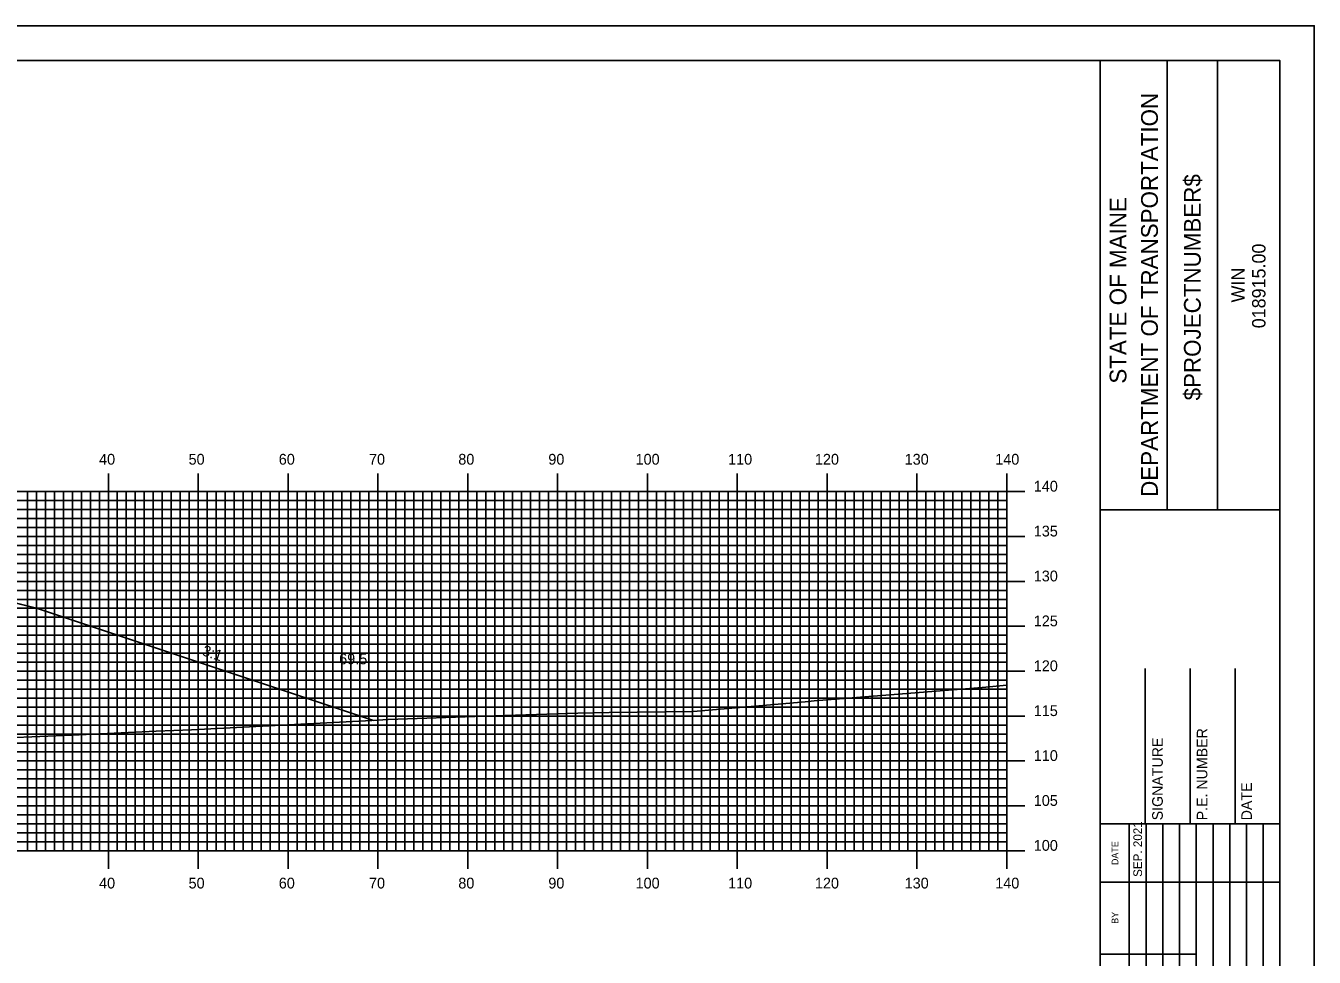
# Model space of a CAD drawing. Extents: x 1781860 to 1782203, y 442591 to 442811.
# Drawn here: x 1782056.7 to 1782200.1, y 442706.8 to 442810.5 of the extents above; entities that cross this region are included whole.
import ezdxf

# ---------------------------------------------------------------- set-up
doc = ezdxf.new("R2010")
doc.units = 0
for name, color, linetype in [('ANNOTATION', 7, 'Continuous'), ('BORDER', 7, 'Continuous'), ('D_Roadway_Centerline', 7, 'Continuous'), ('D_Roadway_SlopeLines', 7, 'Continuous'), ('D_Text_Standard', 7, 'Continuous'), ('H_V ANNOTATION', 7, 'Continuous'), ('MAJOR', 7, 'Continuous'), ('MINOR', 7, 'Continuous'), ('PLOT BOUNDARY', 7, 'Continuous'), ('S_Roadway_Centerline', 7, 'Continuous')]:
    doc.layers.add(name, color=color, linetype=linetype)

msp = doc.modelspace()

# ---------------------------------------------------------------- linework, layer by layer
at = {"layer": 'BORDER'}
for p, q in [((1782176.32, 442596.67), (1782176.32, 442806.67)), ((1782183.78, 442756.66), (1782183.78, 442806.66)), ((1782189.37, 442756.66), (1782189.37, 442806.66)), ((1782176.32, 442756.65), (1782196.32, 442756.65)), ((1782181.32, 442721.67), (1782181.32, 442738.97)), ((1782186.32, 442721.67), (1782186.32, 442738.97)), ((1782191.32, 442721.67), (1782191.32, 442738.97)), ((1782176.32, 442721.67), (1782196.32, 442721.67))]:
    msp.add_line(p, q, dxfattribs=at)
msp.add_lwpolyline([(1781876.32, 442596.67), (1782196.32, 442596.67), (1782196.32, 442806.67), (1781876.32, 442806.67)], close=True, dxfattribs=at)
for points in [[(1782179.55, 442715.17), (1782179.55, 442721.67)], [(1782181.42, 442686.68), (1782181.42, 442721.67)], [(1782183.28, 442721.67), (1782183.28, 442686.68)], [(1782185.14, 442686.68), (1782185.14, 442721.67)], [(1782187.01, 442686.68), (1782187.01, 442721.67)], [(1782188.87, 442686.68), (1782188.87, 442721.67)], [(1782190.73, 442686.68), (1782190.73, 442721.67)], [(1782192.6, 442686.68), (1782192.6, 442721.67)], [(1782194.46, 442686.68), (1782194.46, 442721.67)], [(1782179.55, 442686.68), (1782179.55, 442720.26)], [(1782176.32, 442715.17), (1782196.32, 442715.17)], [(1782176.32, 442707.17), (1782179.55, 442707.17)], [(1782179.55, 442707.17), (1782187, 442707.17)]]:
    msp.add_lwpolyline(points, dxfattribs=at)
at = {"layer": 'D_Roadway_Centerline'}
msp.add_lwpolyline([(1781943.4, 442728.84), (1781993.92, 442745.68), (1781995.75, 442746.13), (1782005.92, 442748.68), (1782013.92, 442749), (1782025.92, 442749.24), (1782037.92, 442749), (1782045.92, 442748.68), (1782056.09, 442746.13), (1782057.92, 442745.68), (1782095.42, 442733.18)], dxfattribs=at)
at = {"layer": 'D_Roadway_SlopeLines'}
msp.add_lwpolyline([(1782045.92, 442748.68), (1782057.92, 442745.68), (1782095.42, 442733.18)], dxfattribs=at)
at = {"layer": 'MAJOR'}
for p, q in [((1782065.92, 442760.67), (1782065.92, 442758.67)), ((1782075.92, 442760.67), (1782075.92, 442758.67)), ((1782085.92, 442760.67), (1782085.92, 442758.67)), ((1782095.92, 442760.67), (1782095.92, 442758.67)), ((1782105.92, 442760.67), (1782105.92, 442758.67)), ((1782115.92, 442760.67), (1782115.92, 442758.67)), ((1782125.92, 442760.67), (1782125.92, 442758.67)), ((1782135.92, 442760.67), (1782135.92, 442758.67)), ((1782145.92, 442760.67), (1782145.92, 442758.67)), ((1782155.92, 442760.67), (1782155.92, 442758.67)), ((1782165.92, 442760.67), (1782165.92, 442758.67)), ((1781885.92, 442758.67), (1782165.92, 442758.67)), ((1781885.92, 442758.67), (1782165.92, 442758.67)), ((1782065.92, 442718.67), (1782065.92, 442758.67)), ((1782075.92, 442718.67), (1782075.92, 442758.67)), ((1782085.92, 442718.67), (1782085.92, 442758.67)), ((1782095.92, 442718.67), (1782095.92, 442758.67)), ((1782105.92, 442718.67), (1782105.92, 442758.67)), ((1782115.92, 442718.67), (1782115.92, 442758.67)), ((1782125.92, 442718.67), (1782125.92, 442758.67)), ((1782135.92, 442718.67), (1782135.92, 442758.67)), ((1782145.92, 442718.67), (1782145.92, 442758.67)), ((1782155.92, 442718.67), (1782155.92, 442758.67)), ((1782167.92, 442758.67), (1782163.92, 442758.67)), ((1782165.92, 442718.67), (1782165.92, 442758.67)), ((1782165.92, 442718.67), (1782165.92, 442758.67)), ((1781885.92, 442753.67), (1782165.92, 442753.67)), ((1782167.92, 442753.67), (1782163.92, 442753.67)), ((1781885.92, 442748.67), (1782165.92, 442748.67)), ((1782167.92, 442748.67), (1782163.92, 442748.67)), ((1781885.92, 442743.67), (1782165.92, 442743.67)), ((1782167.92, 442743.67), (1782163.92, 442743.67)), ((1781885.92, 442738.67), (1782165.92, 442738.67)), ((1782167.92, 442738.67), (1782163.92, 442738.67)), ((1781885.92, 442733.67), (1782165.92, 442733.67)), ((1782167.92, 442733.67), (1782163.92, 442733.67)), ((1781885.92, 442728.67), (1782165.92, 442728.67)), ((1782167.92, 442728.67), (1782163.92, 442728.67)), ((1781885.92, 442723.67), (1782165.92, 442723.67)), ((1782167.92, 442723.67), (1782163.92, 442723.67)), ((1781885.92, 442718.67), (1782165.92, 442718.67)), ((1781885.92, 442718.67), (1782165.92, 442718.67)), ((1782065.92, 442716.66), (1782065.92, 442718.67)), ((1782075.92, 442716.66), (1782075.92, 442718.67)), ((1782085.92, 442716.66), (1782085.92, 442718.67)), ((1782095.92, 442716.66), (1782095.92, 442718.67)), ((1782105.92, 442716.66), (1782105.92, 442718.67)), ((1782115.92, 442716.66), (1782115.92, 442718.67)), ((1782125.92, 442716.66), (1782125.92, 442718.67)), ((1782135.92, 442716.66), (1782135.92, 442718.67)), ((1782145.92, 442716.66), (1782145.92, 442718.67)), ((1782155.92, 442716.66), (1782155.92, 442718.67)), ((1782167.92, 442718.67), (1782163.92, 442718.67)), ((1782165.92, 442716.66), (1782165.92, 442718.67))]:
    msp.add_line(p, q, dxfattribs=at)
at = {"layer": 'MINOR'}
for p, q in [((1782056.92, 442718.67), (1782056.92, 442758.67)), ((1782057.92, 442718.67), (1782057.92, 442758.67)), ((1782058.92, 442718.67), (1782058.92, 442758.67)), ((1782059.92, 442718.67), (1782059.92, 442758.67)), ((1782060.92, 442718.67), (1782060.92, 442758.67)), ((1782061.92, 442718.67), (1782061.92, 442758.67)), ((1782062.92, 442718.67), (1782062.92, 442758.67)), ((1782063.92, 442718.67), (1782063.92, 442758.67)), ((1782064.92, 442718.67), (1782064.92, 442758.67)), ((1782066.92, 442718.67), (1782066.92, 442758.67)), ((1782067.92, 442718.67), (1782067.92, 442758.67)), ((1782068.92, 442718.67), (1782068.92, 442758.67)), ((1782069.92, 442718.67), (1782069.92, 442758.67)), ((1782070.92, 442718.67), (1782070.92, 442758.67)), ((1782071.92, 442718.67), (1782071.92, 442758.67)), ((1782072.92, 442718.67), (1782072.92, 442758.67)), ((1782073.92, 442718.67), (1782073.92, 442758.67)), ((1782074.92, 442718.67), (1782074.92, 442758.67)), ((1782076.92, 442718.67), (1782076.92, 442758.67)), ((1782077.92, 442718.67), (1782077.92, 442758.67)), ((1782078.92, 442718.67), (1782078.92, 442758.67)), ((1782079.92, 442718.67), (1782079.92, 442758.67)), ((1782080.92, 442718.67), (1782080.92, 442758.67)), ((1782081.92, 442718.67), (1782081.92, 442758.67)), ((1782082.92, 442718.67), (1782082.92, 442758.67)), ((1782083.92, 442718.67), (1782083.92, 442758.67)), ((1782084.92, 442718.67), (1782084.92, 442758.67)), ((1782086.92, 442718.67), (1782086.92, 442758.67)), ((1782087.92, 442718.67), (1782087.92, 442758.67)), ((1782088.92, 442718.67), (1782088.92, 442758.67)), ((1782089.92, 442718.67), (1782089.92, 442758.67)), ((1782090.92, 442718.67), (1782090.92, 442758.67)), ((1782091.92, 442718.67), (1782091.92, 442758.67)), ((1782092.92, 442718.67), (1782092.92, 442758.67)), ((1782093.92, 442718.67), (1782093.92, 442758.67)), ((1782094.92, 442718.67), (1782094.92, 442758.67)), ((1782096.92, 442718.67), (1782096.92, 442758.67)), ((1782097.92, 442718.67), (1782097.92, 442758.67)), ((1782098.92, 442718.67), (1782098.92, 442758.67)), ((1782099.92, 442718.67), (1782099.92, 442758.67)), ((1782100.92, 442718.67), (1782100.92, 442758.67)), ((1782101.92, 442718.67), (1782101.92, 442758.67)), ((1782102.92, 442718.67), (1782102.92, 442758.67)), ((1782103.92, 442718.67), (1782103.92, 442758.67)), ((1782104.92, 442718.67), (1782104.92, 442758.67)), ((1782106.92, 442718.67), (1782106.92, 442758.67)), ((1782107.92, 442718.67), (1782107.92, 442758.67)), ((1782108.92, 442718.67), (1782108.92, 442758.67)), ((1782109.92, 442718.67), (1782109.92, 442758.67)), ((1782110.92, 442718.67), (1782110.92, 442758.67)), ((1782111.92, 442718.67), (1782111.92, 442758.67)), ((1782112.92, 442718.67), (1782112.92, 442758.67)), ((1782113.92, 442718.67), (1782113.92, 442758.67)), ((1782114.92, 442718.67), (1782114.92, 442758.67)), ((1782116.92, 442718.67), (1782116.92, 442758.67)), ((1782117.92, 442718.67), (1782117.92, 442758.67)), ((1782118.92, 442718.67), (1782118.92, 442758.67)), ((1782119.92, 442718.67), (1782119.92, 442758.67)), ((1782120.92, 442718.67), (1782120.92, 442758.67)), ((1782121.92, 442718.67), (1782121.92, 442758.67)), ((1782122.92, 442718.67), (1782122.92, 442758.67)), ((1782123.92, 442718.67), (1782123.92, 442758.67)), ((1782124.92, 442718.67), (1782124.92, 442758.67)), ((1782126.92, 442718.67), (1782126.92, 442758.67)), ((1782127.92, 442718.67), (1782127.92, 442758.67)), ((1782128.92, 442718.67), (1782128.92, 442758.67)), ((1782129.92, 442718.67), (1782129.92, 442758.67)), ((1782130.92, 442718.67), (1782130.92, 442758.67)), ((1782131.92, 442718.67), (1782131.92, 442758.67)), ((1782132.92, 442718.67), (1782132.92, 442758.67)), ((1782133.92, 442718.67), (1782133.92, 442758.67)), ((1782134.92, 442718.67), (1782134.92, 442758.67)), ((1782136.92, 442718.67), (1782136.92, 442758.67)), ((1782137.92, 442718.67), (1782137.92, 442758.67)), ((1782138.92, 442718.67), (1782138.92, 442758.67)), ((1782139.92, 442718.67), (1782139.92, 442758.67)), ((1782140.92, 442718.67), (1782140.92, 442758.67)), ((1782141.92, 442718.67), (1782141.92, 442758.67)), ((1782142.92, 442718.67), (1782142.92, 442758.67)), ((1782143.92, 442718.67), (1782143.92, 442758.67)), ((1782144.92, 442718.67), (1782144.92, 442758.67)), ((1782146.92, 442718.67), (1782146.92, 442758.67)), ((1782147.92, 442718.67), (1782147.92, 442758.67)), ((1782148.92, 442718.67), (1782148.92, 442758.67)), ((1782149.92, 442718.67), (1782149.92, 442758.67)), ((1782150.92, 442718.67), (1782150.92, 442758.67)), ((1782151.92, 442718.67), (1782151.92, 442758.67)), ((1782152.92, 442718.67), (1782152.92, 442758.67)), ((1782153.92, 442718.67), (1782153.92, 442758.67)), ((1782154.92, 442718.67), (1782154.92, 442758.67)), ((1782156.92, 442718.67), (1782156.92, 442758.67)), ((1782157.92, 442718.67), (1782157.92, 442758.67)), ((1782158.92, 442718.67), (1782158.92, 442758.67)), ((1782159.92, 442718.67), (1782159.92, 442758.67)), ((1782160.92, 442718.67), (1782160.92, 442758.67)), ((1782161.92, 442718.67), (1782161.92, 442758.67)), ((1782162.92, 442718.67), (1782162.92, 442758.67)), ((1782163.92, 442718.67), (1782163.92, 442758.67)), ((1782164.92, 442718.67), (1782164.92, 442758.67)), ((1781885.92, 442757.67), (1782165.92, 442757.67)), ((1782165.92, 442757.67), (1782163.92, 442757.67)), ((1781885.92, 442756.67), (1782165.92, 442756.67)), ((1781885.92, 442755.67), (1782165.92, 442755.67)), ((1782165.92, 442756.67), (1782163.92, 442756.67)), ((1782165.92, 442755.67), (1782163.92, 442755.67)), ((1781885.92, 442754.67), (1782165.92, 442754.67)), ((1782165.92, 442754.67), (1782163.92, 442754.67)), ((1781885.92, 442752.67), (1782165.92, 442752.67)), ((1782165.92, 442752.67), (1782163.92, 442752.67)), ((1781885.92, 442751.67), (1782165.92, 442751.67)), ((1782165.92, 442751.67), (1782163.92, 442751.67)), ((1781885.92, 442750.67), (1782165.92, 442750.67)), ((1782165.92, 442750.67), (1782163.92, 442750.67)), ((1781885.92, 442749.67), (1782165.92, 442749.67)), ((1782165.92, 442749.67), (1782163.92, 442749.67)), ((1781885.92, 442747.67), (1782165.92, 442747.67)), ((1782165.92, 442747.67), (1782163.92, 442747.67)), ((1781885.92, 442746.67), (1782165.92, 442746.67)), ((1781885.92, 442745.67), (1782165.92, 442745.67)), ((1782165.92, 442746.67), (1782163.92, 442746.67)), ((1782165.92, 442745.67), (1782163.92, 442745.67)), ((1781885.92, 442744.67), (1782165.92, 442744.67)), ((1782165.92, 442744.67), (1782163.92, 442744.67)), ((1781885.92, 442742.67), (1782165.92, 442742.67)), ((1782165.92, 442742.67), (1782163.92, 442742.67)), ((1781885.92, 442741.67), (1782165.92, 442741.67)), ((1782165.92, 442741.67), (1782163.92, 442741.67)), ((1781885.92, 442740.67), (1782165.92, 442740.67)), ((1782165.92, 442740.67), (1782163.92, 442740.67)), ((1781885.92, 442739.67), (1782165.92, 442739.67)), ((1782165.92, 442739.67), (1782163.92, 442739.67)), ((1781885.92, 442737.67), (1782165.92, 442737.67)), ((1782165.92, 442737.67), (1782163.92, 442737.67)), ((1781885.92, 442736.67), (1782165.92, 442736.67)), ((1781885.92, 442735.67), (1782165.92, 442735.67)), ((1782165.92, 442736.67), (1782163.92, 442736.67)), ((1782165.92, 442735.67), (1782163.92, 442735.67)), ((1781885.92, 442734.67), (1782165.92, 442734.67)), ((1782165.92, 442734.67), (1782163.92, 442734.67)), ((1781885.92, 442732.67), (1782165.92, 442732.67)), ((1782165.92, 442732.67), (1782163.92, 442732.67)), ((1781885.92, 442731.67), (1782165.92, 442731.67)), ((1782165.92, 442731.67), (1782163.92, 442731.67)), ((1781885.92, 442730.67), (1782165.92, 442730.67)), ((1782165.92, 442730.67), (1782163.92, 442730.67)), ((1781885.92, 442729.67), (1782165.92, 442729.67)), ((1782165.92, 442729.67), (1782163.92, 442729.67)), ((1781885.92, 442727.67), (1782165.92, 442727.67)), ((1782165.92, 442727.67), (1782163.92, 442727.67)), ((1781885.92, 442726.67), (1782165.92, 442726.67)), ((1781885.92, 442725.67), (1782165.92, 442725.67)), ((1782165.92, 442726.67), (1782163.92, 442726.67)), ((1782165.92, 442725.67), (1782163.92, 442725.67)), ((1781885.92, 442724.67), (1782165.92, 442724.67)), ((1782165.92, 442724.67), (1782163.92, 442724.67)), ((1781885.92, 442722.67), (1782165.92, 442722.67)), ((1782165.92, 442722.67), (1782163.92, 442722.67)), ((1781885.92, 442721.67), (1782165.92, 442721.67)), ((1782165.92, 442721.67), (1782163.92, 442721.67)), ((1781885.92, 442720.67), (1782165.92, 442720.67)), ((1781885.92, 442719.67), (1782165.92, 442719.67)), ((1782165.92, 442720.67), (1782163.92, 442720.67)), ((1782165.92, 442719.67), (1782163.92, 442719.67))]:
    msp.add_line(p, q, dxfattribs=at)
at = {"layer": 'PLOT BOUNDARY'}
msp.add_lwpolyline([(1781860.13, 442590.55), (1782200.13, 442590.55), (1782200.13, 442810.55), (1781860.13, 442810.55)], close=True, dxfattribs=at)
at = {"layer": 'S_Roadway_Centerline'}
msp.add_lwpolyline([(1782043.87, 442730.79), (1782061.88, 442731.55), (1782071.24, 442731.98), (1782075.17, 442732.13), (1782095.26, 442733.17), (1782097.08, 442733.28), (1782107.79, 442733.65), (1782118.17, 442734), (1782121.65, 442734.05), (1782131.01, 442734.17), (1782143.49, 442735.25), (1782144.48, 442735.37), (1782145.45, 442735.44), (1782163.16, 442736.87), (1782165.92, 442737.12)], dxfattribs=at)

# ---------------------------------------------------------------- texts
at = {"layer": 'ANNOTATION'}
msp.add_text('3:1', height=1.2, rotation=341.5652, dxfattribs=at).set_placement((1782076.27, 442740.47))
at = {"layer": 'BORDER'}
for s, height, p in [('DEPARTMENT OF TRANSPORTATION', 1.8635, (1782182.73, 442758.08)), ('$PROJECTNUMBER$', 1.8635, (1782187.5, 442768.82)), ('STATE OF MAINE', 1.8635, (1782179.23, 442770.69)), ('018915.00', 1.491, (1782194.71, 442776.86)), ('WIN', 1.491, (1782192.39, 442779.73)), ('SIGNATURE', 1.181, (1782183.28, 442722.06)), ('P.E. NUMBER', 1.1811, (1782188.24, 442722.06)), ('DATE', 1.181, (1782193.2, 442722.06)), ('SEP. 2021', 0.969, (1782180.97, 442715.76)), ('DATE', 0.743, (1782178.33, 442717.08)), ('BY', 0.743, (1782178.33, 442710.54))]:
    msp.add_text(s, height=height, rotation=90, dxfattribs=at).set_placement(p)
at = {"layer": 'D_Text_Standard'}
msp.add_text("69.5'", height=1.2, dxfattribs=at).set_placement((1782091.61, 442739.44))
at = {"layer": 'H_V ANNOTATION'}
for s, p in [('40', (1782064.89, 442761.67)), ('50', (1782074.85, 442761.67)), ('60', (1782084.89, 442761.67)), ('70', (1782094.93, 442761.67)), ('80', (1782104.87, 442761.67)), ('90', (1782114.89, 442761.67)), ('100', (1782124.6, 442761.67)), ('110', (1782134.9, 442761.67)), ('120', (1782144.56, 442761.67)), ('130', (1782154.55, 442761.67)), ('140', (1782164.63, 442761.67)), ('140', (1782168.92, 442758.67)), ('135', (1782168.92, 442753.67)), ('130', (1782168.92, 442748.67)), ('125', (1782168.92, 442743.67)), ('120', (1782168.92, 442738.67)), ('115', (1782168.92, 442733.67)), ('110', (1782168.92, 442728.67)), ('105', (1782168.92, 442723.67)), ('100', (1782168.92, 442718.67)), ('40', (1782064.89, 442714.47)), ('50', (1782074.85, 442714.47)), ('60', (1782084.89, 442714.47)), ('70', (1782094.93, 442714.47)), ('80', (1782104.87, 442714.47)), ('90', (1782114.89, 442714.47)), ('100', (1782124.6, 442714.47)), ('110', (1782134.9, 442714.47)), ('120', (1782144.56, 442714.47)), ('130', (1782154.55, 442714.47)), ('140', (1782164.63, 442714.47))]:
    msp.add_text(s, height=1.2, dxfattribs=at).set_placement(p)

doc.saveas('drawing.dxf')
